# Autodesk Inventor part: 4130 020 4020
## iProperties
Company: M20x1,5 / M22x1,5
Created: 2008-12
Part Number: 4130 020 4020
Material: 2.1020 CuSn6
Document SubType Name: Modellieren
Designer: TMT
Manufacturer: Standard
Standards Organization: Custom
Density: 8.8 g/cm^3
Description: Gewindeeinsatz HELICOIL plus M20x1,5
Vendor: BÖLHOFF
Mass: 19.4171 g
Surface Area: 26.6527 cm^2
Volume: 2.20649 cm^3
Author: TMT
Comments: BÖLHOFF
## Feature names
1. Extrusion2
2. Bohrung1 [Hole]
